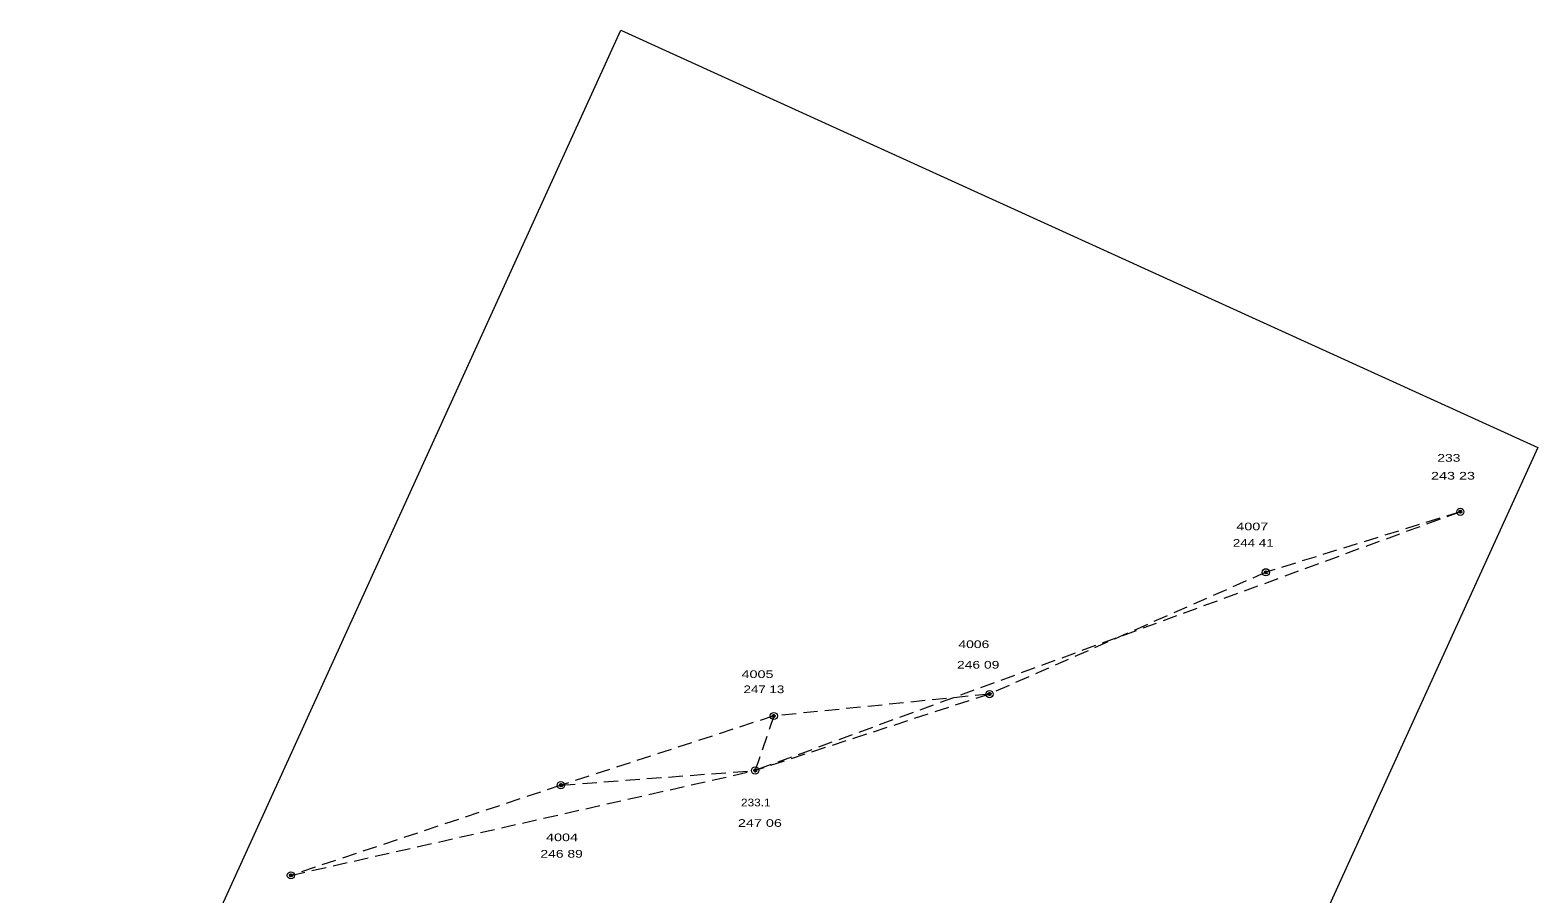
# Model space of a CAD drawing. Extents: x -597411 to -596783, y -1159250 to -1158536.
# Drawn here: x -597411 to -596783, y -1158896 to -1158536 of the extents above; entities that cross this region are included whole.
import ezdxf
from ezdxf.enums import TextEntityAlignment as Align

# ---------------------------------------------------------------- set-up
doc = ezdxf.new("R2010")
doc.units = 0
doc.header["$LTSCALE"] = 2
doc.header["$PDMODE"] = 32
doc.header["$PDSIZE"] = 1
doc.linetypes.add('MEDIUM_DASHED', pattern=[4.5, 3, -1.5])
for name, color, linetype, lineweight in [('11', 7, 'MEDIUM_DASHED', 13), ('60', 7, 'Continuous', 13), ('62', 7, 'Continuous', 13)]:
    doc.layers.add(name, color=color, linetype=linetype, lineweight=lineweight)
for name, color, linetype in [('59', 7, 'Continuous'), ('61', 7, 'Continuous'), ('63', 7, 'Continuous')]:
    doc.layers.add(name, color=color, linetype=linetype)

msp = doc.modelspace()

# ---------------------------------------------------------------- linework, layer by layer
at = {"layer": '11'}
for p, q in [((-596815.16, -1158736.6), (-597109.08, -1158844.47)), ((-597011.41, -1158812.63), (-597101.32, -1158821.75)), ((-597101.32, -1158821.75), (-597109.08, -1158844.47))]:
    msp.add_line(p, q, dxfattribs=at)
for points in [[(-596815.16, -1158736.6), (-596896.22, -1158761.82), (-597011.41, -1158812.63), (-597109.08, -1158844.47)], [(-597101.32, -1158821.75), (-597190.08, -1158850.6), (-597109.08, -1158844.47)], [(-597190.08, -1158850.6), (-597302.59, -1158888.2), (-597109.08, -1158844.47)]]:
    msp.add_lwpolyline(points, dxfattribs=at)
at = {"layer": '60'}
for centre, radius in [((-596815.16, -1158736.6), 1.5), ((-596815.16, -1158736.6), 0.2), ((-596896.22, -1158761.82), 1.5), ((-596896.22, -1158761.82), 0.2), ((-597011.41, -1158812.63), 1.5), ((-597011.41, -1158812.63), 0.2), ((-597101.32, -1158821.75), 1.5), ((-597101.32, -1158821.75), 0.2), ((-597109.08, -1158844.47), 1.5), ((-597109.08, -1158844.47), 0.2), ((-597190.08, -1158850.6), 1.5), ((-597190.08, -1158850.6), 0.2), ((-597302.59, -1158888.2), 1.5), ((-597302.59, -1158888.2), 0.2)]:
    msp.add_circle(centre, radius, dxfattribs=at)
at = {"layer": '62'}
msp.add_lwpolyline([(-597165.078, -1158535.742), (-596782.855, -1158709.829), (-597029.064, -1159250.4), (-597411.286, -1159076.313)], close=True, dxfattribs=at)
at = {"layer": '63'}
for p in [(-596815.16, -1158736.6), (-596896.22, -1158761.82), (-597011.41, -1158812.63), (-597101.32, -1158821.75), (-597109.08, -1158844.47), (-597190.08, -1158850.6), (-597302.59, -1158888.2)]:
    msp.add_point(p, dxfattribs=at)

# ---------------------------------------------------------------- texts
at = {"layer": '59'}
for s, width, p in [('243 23 ', 1.4, (-596817.399, -1158723.162)), ('244 41 ', 1.3, (-596900.699, -1158751.181)), ('246 09 ', 1.35, (-597015.329, -1158801.991)), ('247 13 ', 1.3, (-597104.679, -1158812.231)), ('247 06 ', 1.4, (-597106.28, -1158867.986)), ('246 89 ', 1.35, (-597188.96, -1158880.834))]:
    msp.add_text(s, height=3.2, dxfattribs=dict(at, width=width)).set_placement(p, align=Align.CENTER)
at = {"layer": '61'}
for s, width, p in [(' 233', 1.35, (-596826.358, -1158715.724)), (' 4007', 1.4, (-596910.217, -1158744.303)), (' 4006', 1.35, (-597025.967, -1158793.433)), (' 4005', 1.4, (-597116.437, -1158805.913)), (' 233.1', 1.15, (-597116.358, -1158859.428)), (' 4004', 1.4, (-597197.918, -1158873.956))]:
    msp.add_text(s, height=3.2, dxfattribs=dict(at, width=width)).set_placement(p)

doc.saveas('drawing.dxf')
